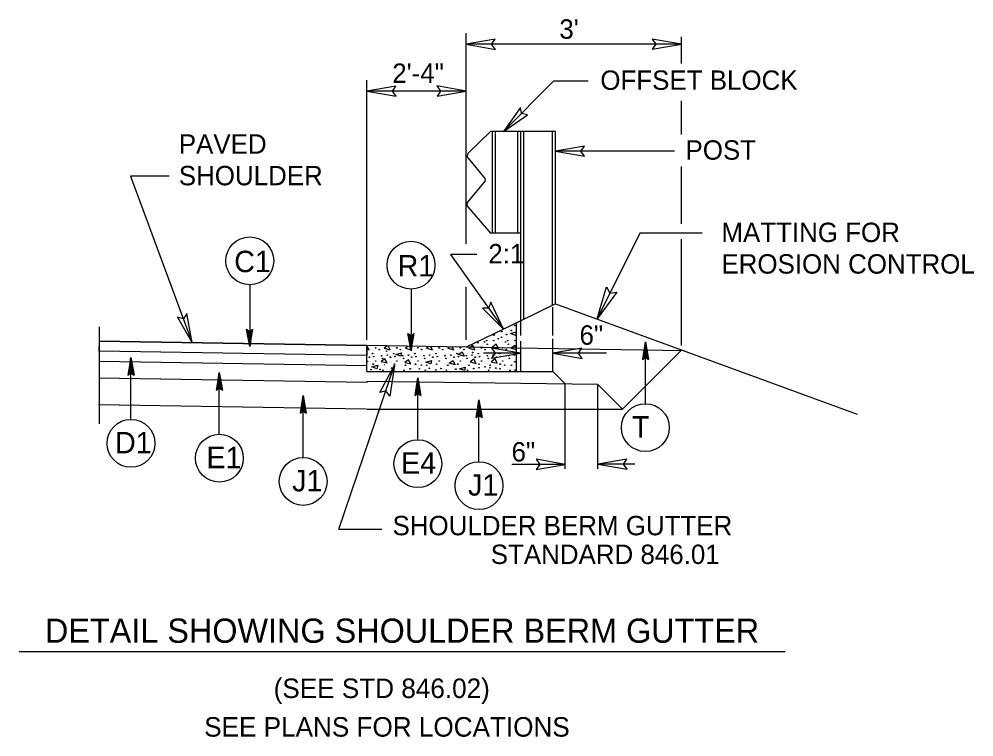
# Model space of a CAD drawing. Extents: x 981824 to 982276, y 44828 to 45204.
# Drawn here: x 982245.3 to 982273.47, y 45182.68 to 45203.85 of the extents above; entities that cross this region are included whole.
import ezdxf

# ---------------------------------------------------------------- set-up
doc = ezdxf.new("R2010")
doc.units = 0
for name, color, linetype in [('Old_Level_1', 7, 'Continuous'), ('Old_Level_2', 7, 'Continuous'), ('Old_Level_20', 7, 'Continuous'), ('Old_Level_3', 7, 'Continuous'), ('Typical Terminator CELL', 7, 'Continuous')]:
    doc.layers.add(name, color=color, linetype=linetype)

msp = doc.modelspace()

# ---------------------------------------------------------------- linework, layer by layer
at = {"layer": 'Old_Level_1'}
for p, q in [((982258.487, 45197.225), (982258.487, 45203.433)), ((982264.837, 45202.542), (982264.837, 45203.331)), ((982264.837, 45203.112), (982258.487, 45203.112)), ((982255.558, 45194.394), (982255.558, 45202.054)), ((982261.066, 45202.018), (982259.584, 45200.532)), ((982262.083, 45202.018), (982261.066, 45202.018)), ((982258.487, 45201.73), (982255.558, 45201.73)), ((982264.837, 45200.446), (982264.837, 45201.441)), ((982258.547, 45199.898), (982259.201, 45200.532)), ((982261.121, 45200.532), (982259.201, 45200.532)), ((982259.267, 45197.534), (982259.267, 45200.532)), ((982259.353, 45197.534), (982259.353, 45200.532)), ((982260.013, 45197.534), (982260.013, 45200.532)), ((982260.1, 45194.956), (982260.1, 45200.532)), ((982260.186, 45194.996), (982260.186, 45200.532)), ((982261.038, 45195.41), (982261.038, 45200.532)), ((982261.121, 45195.454), (982261.121, 45200.532)), ((982264.632, 45199.961), (982261.121, 45199.961)), ((982258.545, 45199.747), (982259.045, 45199.138)), ((982264.837, 45197.816), (982264.837, 45199.501)), ((982249.723, 45199.222), (982248.588, 45199.222)), ((982248.588, 45199.222), (982250.405, 45194.304)), ((982259.047, 45199.079), (982258.53, 45198.455)), ((982258.533, 45198.317), (982259.201, 45197.534)), ((982260.1, 45197.534), (982259.201, 45197.534)), ((982263.61, 45197.539), (982262.348, 45195.006)), ((982265.451, 45197.539), (982263.61, 45197.539)), ((982264.837, 45194.227), (982264.837, 45197.356)), ((982258.803, 45196.91), (982258.026, 45196.91)), ((982258.026, 45196.91), (982259.584, 45194.707)), ((982258.487, 45194.394), (982258.487, 45195.958)), ((982261.121, 45195.454), (982260.1, 45194.953)), ((982261.121, 45195.454), (982270.021, 45192.202)), ((982261.121, 45195.444), (982261.121, 45195.454)), ((982261.047, 45194.52), (982261.047, 45195.356)), ((982260.1, 45194.956), (982258.487, 45194.172)), ((982259.973, 45193.458), (982259.973, 45194.896)), ((982260.1, 45194.52), (982260.1, 45194.956)), ((982252.102, 45194.19), (982252.009, 45194.71)), ((982252.009, 45194.71), (982252.102, 45194.639)), ((982252.027, 45194.7), (982252.102, 45194.19)), ((982252.102, 45194.19), (982252.036, 45194.689)), ((982252.05, 45194.678), (982252.102, 45194.19)), ((982252.102, 45194.19), (982252.065, 45194.671)), ((982252.079, 45194.66), (982252.102, 45194.19)), ((982252.102, 45194.19), (982252.087, 45194.651)), ((982252.102, 45194.19), (982252.191, 45194.71)), ((982252.102, 45194.639), (982252.191, 45194.71)), ((982252.102, 45194.19), (982252.18, 45194.7)), ((982252.168, 45194.689), (982252.102, 45194.19)), ((982252.102, 45194.19), (982252.153, 45194.678)), ((982252.139, 45194.671), (982252.102, 45194.19)), ((982252.102, 45194.19), (982252.128, 45194.66)), ((982252.114, 45194.651), (982252.102, 45194.19)), ((982252.102, 45194.639), (982252.102, 45194.19)), ((982256.86, 45194.064), (982256.765, 45194.58)), ((982256.765, 45194.58), (982256.86, 45194.514)), ((982256.782, 45194.573), (982256.86, 45194.064)), ((982256.86, 45194.064), (982256.794, 45194.564)), ((982256.808, 45194.552), (982256.86, 45194.064)), ((982256.86, 45194.064), (982256.819, 45194.542)), ((982256.831, 45194.536), (982256.86, 45194.064)), ((982256.86, 45194.064), (982256.848, 45194.525)), ((982256.86, 45194.064), (982256.95, 45194.58)), ((982256.86, 45194.514), (982256.95, 45194.58)), ((982256.86, 45194.064), (982256.94, 45194.573)), ((982256.928, 45194.564), (982256.86, 45194.064)), ((982256.86, 45194.064), (982256.914, 45194.552)), ((982256.898, 45194.542), (982256.86, 45194.064)), ((982256.86, 45194.064), (982256.887, 45194.536)), ((982256.871, 45194.525), (982256.86, 45194.064)), ((982259.314, 45194.521), (982259.25, 45194.542)), ((982259.326, 45194.58), (982259.314, 45194.521)), ((982255.558, 45194.221), (982247.668, 45194.351)), ((982256.86, 45194.514), (982256.86, 45194.064)), ((982259.373, 45194.258), (982259.261, 45194.176)), ((982259.44, 45194.134), (982259.373, 45194.258)), ((982260.1, 45193.466), (982260.1, 45194.352)), ((982261.047, 45193.458), (982261.047, 45194.417)), ((982263.775, 45194.331), (982263.685, 45193.814)), ((982263.697, 45193.822), (982263.775, 45194.331)), ((982263.775, 45194.331), (982263.712, 45193.834)), ((982263.723, 45193.842), (982263.775, 45194.331)), ((982263.775, 45194.331), (982263.734, 45193.851)), ((982263.748, 45193.865), (982263.775, 45194.331)), ((982263.775, 45194.331), (982263.76, 45193.871)), ((982263.775, 45194.331), (982263.867, 45193.814)), ((982263.775, 45193.881), (982263.775, 45194.331)), ((982263.789, 45193.871), (982263.775, 45194.331)), ((982263.775, 45194.331), (982263.803, 45193.865)), ((982263.814, 45193.851), (982263.775, 45194.331)), ((982263.775, 45194.331), (982263.826, 45193.842)), ((982263.839, 45193.834), (982263.775, 45194.331)), ((982263.775, 45194.331), (982263.853, 45193.822)), ((982247.655, 45193.958), (982247.655, 45191.909)), ((982255.558, 45193.93), (982247.663, 45194.06)), ((982255.558, 45193.458), (982255.558, 45194.221)), ((982258.487, 45194.172), (982255.558, 45194.221)), ((982255.558, 45193.829), (982255.558, 45194.218)), ((982255.627, 45194.098), (982255.558, 45194.215)), ((982255.558, 45194.112), (982255.627, 45194.098)), ((982256.16, 45194.212), (982256.068, 45194.142)), ((982256.068, 45194.142), (982256.249, 45194.098)), ((982256.249, 45194.098), (982256.185, 45194.212)), ((982256.77, 45194.2), (982256.693, 45194.142)), ((982256.693, 45194.142), (982256.874, 45194.098)), ((982256.874, 45194.098), (982256.818, 45194.2)), ((982257.384, 45194.189), (982257.317, 45194.142)), ((982257.317, 45194.142), (982257.496, 45194.098)), ((982257.496, 45194.098), (982257.447, 45194.186)), ((982257.991, 45194.178), (982257.942, 45194.142)), ((982257.942, 45194.142), (982258.123, 45194.098)), ((982258.123, 45194.098), (982258.078, 45194.176)), ((982259.973, 45194.148), (982258.487, 45194.172)), ((982258.68, 45194.222), (982258.566, 45194.142)), ((982258.566, 45194.142), (982258.746, 45194.098)), ((982258.746, 45194.098), (982258.68, 45194.222)), ((982260.093, 45193.995), (982259.002, 45193.995)), ((982259.261, 45194.176), (982259.44, 45194.134)), ((982259.927, 45194.222), (982259.812, 45194.142)), ((982259.812, 45194.142), (982259.973, 45194.105)), ((982259.973, 45194.141), (982259.927, 45194.222)), ((982264.92, 45194.066), (982259.973, 45194.148)), ((982262.626, 45193.995), (982261.047, 45193.995)), ((982264.818, 45194.067), (982263.102, 45192.347)), ((982255.558, 45193.625), (982247.658, 45193.755)), ((982248.596, 45193.867), (982248.506, 45193.347)), ((982248.521, 45193.359), (982248.596, 45193.867)), ((982248.596, 45193.867), (982248.533, 45193.37)), ((982248.544, 45193.376), (982248.596, 45193.867)), ((982248.596, 45193.867), (982248.558, 45193.388)), ((982248.572, 45193.395), (982248.596, 45193.867)), ((982248.596, 45193.867), (982248.584, 45193.405)), ((982248.596, 45193.867), (982248.688, 45193.347)), ((982248.596, 45193.417), (982248.596, 45193.867)), ((982248.611, 45193.405), (982248.596, 45193.867)), ((982248.596, 45193.867), (982248.625, 45193.395)), ((982248.64, 45193.388), (982248.596, 45193.867)), ((982248.596, 45193.867), (982248.65, 45193.376)), ((982248.664, 45193.37), (982248.596, 45193.867)), ((982248.596, 45193.867), (982248.677, 45193.359)), ((982256.091, 45193.832), (982255.981, 45193.752)), ((982255.981, 45193.752), (982256.16, 45193.708)), ((982256.16, 45193.708), (982256.091, 45193.832)), ((982256.79, 45193.805), (982256.679, 45193.724)), ((982256.679, 45193.724), (982256.856, 45193.68)), ((982256.856, 45193.68), (982256.79, 45193.805)), ((982258.714, 45193.817), (982258.602, 45193.738)), ((982258.602, 45193.738), (982258.783, 45193.692)), ((982258.783, 45193.692), (982258.714, 45193.817)), ((982259.339, 45193.826), (982259.227, 45193.746)), ((982259.227, 45193.746), (982259.405, 45193.704)), ((982259.405, 45193.704), (982259.339, 45193.826)), ((982263.685, 45193.814), (982263.775, 45193.881)), ((982263.775, 45193.881), (982263.867, 45193.814)), ((982248.506, 45193.347), (982248.596, 45193.417)), ((982248.596, 45193.417), (982248.688, 45193.347)), ((982251.204, 45193.429), (982251.115, 45192.91)), ((982251.129, 45192.92), (982251.204, 45193.429)), ((982251.204, 45193.429), (982251.14, 45192.932)), ((982251.152, 45192.938), (982251.204, 45193.429)), ((982251.204, 45193.429), (982251.166, 45192.949)), ((982251.181, 45192.956), (982251.204, 45193.429)), ((982251.204, 45193.429), (982251.192, 45192.967)), ((982251.204, 45193.429), (982251.296, 45192.91)), ((982251.204, 45192.978), (982251.204, 45193.429)), ((982251.218, 45192.967), (982251.204, 45193.429)), ((982251.204, 45193.429), (982251.232, 45192.956)), ((982251.247, 45192.949), (982251.204, 45193.429)), ((982251.204, 45193.429), (982251.259, 45192.938)), ((982251.271, 45192.932), (982251.204, 45193.429)), ((982251.204, 45193.429), (982251.284, 45192.92)), ((982254.73, 45188.8), (982256.372, 45193.639)), ((982255.558, 45193.458), (982259.973, 45193.458)), ((982259.973, 45193.458), (982261.047, 45193.458)), ((982261.047, 45193.458), (982261.412, 45193.091)), ((982255.558, 45193.127), (982247.651, 45193.257)), ((982262.375, 45193.075), (982255.558, 45193.162)), ((982255.558, 45193.162), (982255.558, 45193.127)), ((982257.059, 45193.267), (982256.97, 45192.748)), ((982256.984, 45192.758), (982257.059, 45193.267)), ((982257.059, 45193.267), (982256.995, 45192.77)), ((982257.007, 45192.776), (982257.059, 45193.267)), ((982257.059, 45193.267), (982257.021, 45192.787)), ((982257.036, 45192.794), (982257.059, 45193.267)), ((982257.059, 45193.267), (982257.047, 45192.805)), ((982257.059, 45193.267), (982257.151, 45192.748)), ((982257.059, 45192.816), (982257.059, 45193.267)), ((982257.073, 45192.805), (982257.059, 45193.267)), ((982257.059, 45193.267), (982257.087, 45192.794)), ((982257.102, 45192.787), (982257.059, 45193.267)), ((982257.059, 45193.267), (982257.114, 45192.776)), ((982257.126, 45192.77), (982257.059, 45193.267)), ((982257.059, 45193.267), (982257.139, 45192.758)), ((982251.115, 45192.91), (982251.204, 45192.978)), ((982251.204, 45192.978), (982251.296, 45192.91)), ((982261.412, 45190.581), (982261.412, 45193.091)), ((982262.375, 45193.075), (982263.102, 45192.347)), ((982262.375, 45190.589), (982262.375, 45193.075)), ((982253.676, 45192.744), (982253.587, 45192.225)), ((982253.601, 45192.235), (982253.676, 45192.744)), ((982253.676, 45192.744), (982253.612, 45192.247)), ((982253.624, 45192.253), (982253.676, 45192.744)), ((982253.676, 45192.744), (982253.638, 45192.264)), ((982253.653, 45192.271), (982253.676, 45192.744)), ((982253.676, 45192.744), (982253.664, 45192.282)), ((982253.676, 45192.744), (982253.768, 45192.225)), ((982253.676, 45192.293), (982253.676, 45192.744)), ((982253.69, 45192.282), (982253.676, 45192.744)), ((982253.676, 45192.744), (982253.704, 45192.271)), ((982253.719, 45192.264), (982253.676, 45192.744)), ((982253.676, 45192.744), (982253.731, 45192.253)), ((982253.743, 45192.247), (982253.676, 45192.744)), ((982253.676, 45192.744), (982253.756, 45192.235)), ((982256.97, 45192.748), (982257.059, 45192.816)), ((982257.059, 45192.816), (982257.151, 45192.748)), ((982258.864, 45192.617), (982258.775, 45192.096)), ((982258.789, 45192.108), (982258.864, 45192.617)), ((982258.864, 45192.617), (982258.8, 45192.12)), ((982258.812, 45192.125), (982258.864, 45192.617)), ((982258.864, 45192.617), (982258.827, 45192.137)), ((982258.841, 45192.144), (982258.864, 45192.617)), ((982258.864, 45192.617), (982258.853, 45192.154)), ((982258.864, 45192.617), (982258.956, 45192.096)), ((982258.864, 45192.166), (982258.864, 45192.617)), ((982258.878, 45192.154), (982258.864, 45192.617)), ((982258.864, 45192.617), (982258.893, 45192.144)), ((982258.907, 45192.137), (982258.864, 45192.617)), ((982258.864, 45192.617), (982258.919, 45192.125)), ((982258.932, 45192.12), (982258.864, 45192.617)), ((982258.864, 45192.617), (982258.944, 45192.108)), ((982255.54, 45192.347), (982247.637, 45192.477)), ((982253.587, 45192.225), (982253.676, 45192.293)), ((982253.676, 45192.293), (982253.768, 45192.225)), ((982255.558, 45192.347), (982263.102, 45192.347)), ((982258.775, 45192.096), (982258.864, 45192.166)), ((982258.864, 45192.166), (982258.956, 45192.096)), ((982261.412, 45190.717), (982259.833, 45190.717)), ((982263.465, 45190.725), (982262.375, 45190.725)), ((982254.73, 45188.8), (982255.994, 45188.8))]:
    msp.add_line(p, q, dxfattribs=at)
msp.add_lwpolyline([(982247.655, 45194.772), (982247.655, 45193.882)], dxfattribs=at)
for points in [[(982259.791, 45194.574), (982259.959, 45194.622), (982259.938, 45194.521)], [(982247.668, 45194.351), (982255.558, 45194.221), (982255.558, 45193.93), (982247.663, 45194.06)], [(982256.411, 45193.957), (982256.579, 45194.005), (982256.558, 45193.904)], [(982258.254, 45193.955), (982258.365, 45194.033), (982258.431, 45193.907)], [(982257.296, 45193.734), (982257.464, 45193.782), (982257.443, 45193.681)], [(982257.983, 45193.703), (982258.094, 45193.781), (982258.16, 45193.655)], [(982255.708, 45193.591), (982255.876, 45193.639), (982255.855, 45193.538)], [(982258.289, 45193.534), (982258.457, 45193.582), (982258.436, 45193.481)]]:
    msp.add_lwpolyline(points, close=True, dxfattribs=at)
for centre in [(982259.922, 45194.812), (982259.539, 45194.635), (982259.676, 45194.547), (982259.82, 45194.666), (982258.837, 45194.304), (982259.028, 45194.329), (982259.089, 45194.367), (982259.108, 45194.26), (982259.302, 45194.367), (982259.434, 45194.422), (982259.533, 45194.466), (982259.652, 45194.329), (982259.714, 45194.367), (982259.732, 45194.26), (982259.927, 45194.367), (982255.724, 45193.984), (982255.817, 45194.154), (982255.923, 45194.103), (982256.141, 45194.058), (982256.349, 45193.984), (982256.442, 45194.154), (982256.547, 45194.103), (982256.973, 45193.984), (982257.066, 45194.154), (982257.172, 45194.103), (982257.598, 45193.984), (982257.691, 45194.154), (982257.796, 45194.103), (982258.222, 45193.984), (982258.315, 45194.154), (982258.421, 45194.103), (982258.677, 45194.018), (982258.847, 45193.984), (982258.94, 45194.154), (982259.045, 45194.103), (982259.471, 45193.984), (982259.564, 45194.154), (982259.67, 45194.103), (982255.576, 45193.755), (982255.63, 45193.879), (982255.743, 45193.673), (982255.761, 45193.897), (982255.817, 45193.767), (982255.992, 45193.922), (982256.017, 45193.842), (982256.161, 45193.941), (982256.255, 45193.879), (982256.368, 45193.673), (982256.385, 45193.897), (982256.442, 45193.767), (982256.616, 45193.922), (982256.641, 45193.842), (982256.785, 45193.941), (982256.879, 45193.879), (982256.992, 45193.673), (982257.01, 45193.897), (982257.066, 45193.767), (982257.241, 45193.922), (982257.266, 45193.842), (982257.41, 45193.941), (982257.504, 45193.879), (982257.617, 45193.673), (982257.634, 45193.897), (982257.691, 45193.767), (982257.865, 45193.922), (982257.89, 45193.842), (982258.034, 45193.941), (982258.128, 45193.879), (982258.241, 45193.673), (982258.259, 45193.897), (982258.315, 45193.767), (982258.49, 45193.922), (982258.515, 45193.842), (982258.659, 45193.941), (982258.753, 45193.879), (982258.866, 45193.673), (982258.883, 45193.897), (982258.94, 45193.767), (982259.114, 45193.922), (982259.139, 45193.842), (982259.283, 45193.941), (982259.377, 45193.879), (982259.49, 45193.673), (982259.508, 45193.897), (982259.564, 45193.767), (982259.739, 45193.922), (982259.764, 45193.842), (982259.908, 45193.941), (982259.922, 45193.744), (982255.681, 45193.513), (982255.949, 45193.518), (982256.032, 45193.493), (982256.287, 45193.556), (982256.656, 45193.493), (982256.698, 45193.641), (982256.835, 45193.535), (982257.106, 45193.532), (982257.164, 45193.647), (982257.281, 45193.493), (982257.322, 45193.641), (982257.398, 45193.551), (982257.592, 45193.504), (982257.742, 45193.545), (982257.905, 45193.493), (982257.947, 45193.641), (982258.182, 45193.524), (982258.529, 45193.493), (982258.571, 45193.641), (982258.708, 45193.545), (982258.869, 45193.567), (982259.042, 45193.595), (982259.154, 45193.493), (982259.191, 45193.567), (982259.196, 45193.641), (982259.363, 45193.556), (982259.486, 45193.535), (982259.626, 45193.647), (982259.778, 45193.493), (982259.82, 45193.641), (982259.933, 45193.498)]:
    msp.add_circle(centre, 0.0088, dxfattribs=at)
for centre, radius, start, end in [((982258.626, 45199.82), 0.111, 135.694, 221.3854), ((982259.004, 45199.106), 0.0515, 326.6101, 36.7601), ((982258.621, 45198.388), 0.113, 144.2385, 219.8658), ((982256.073, 45193.641), 0.0088, 351.9822, 186.1383)]:
    msp.add_arc(centre, radius, start, end, dxfattribs=at)
at = {"layer": 'Old_Level_2'}
for p, q in [((982252.102, 45196.018), (982252.102, 45194.19)), ((982256.86, 45195.89), (982256.86, 45194.064)), ((982263.775, 45192.51), (982263.775, 45194.331)), ((982248.596, 45192.04), (982248.596, 45193.867)), ((982251.204, 45191.602), (982251.204, 45193.429)), ((982257.059, 45191.44), (982257.059, 45193.267)), ((982253.676, 45190.917), (982253.676, 45192.744)), ((982258.864, 45190.789), (982258.864, 45192.617))]:
    msp.add_line(p, q, dxfattribs=at)
for centre in [(982252.102, 45196.721), (982256.86, 45196.593), (982263.774, 45191.801), (982248.597, 45191.337), (982251.206, 45190.899), (982257.062, 45190.737), (982253.678, 45190.214), (982258.866, 45190.088)]:
    msp.add_circle(centre, 0.706, dxfattribs=at)
at = {"layer": 'Old_Level_3'}
msp.add_line((982267.904, 45185.19), (982245.296, 45185.19), dxfattribs=at)
at = {"layer": 'Typical Terminator CELL'}
for points in [[(982259.344, 45203.259), (982258.487, 45203.112), (982259.349, 45202.959), (982259.239, 45203.112)], [(982263.979, 45202.964), (982264.837, 45203.112), (982263.974, 45203.264), (982264.084, 45203.112)], [(982256.415, 45201.877), (982255.558, 45201.73), (982256.42, 45201.577), (982256.31, 45201.73)], [(982257.629, 45201.582), (982258.487, 45201.73), (982257.624, 45201.882), (982257.734, 45201.73)], [(982260.086, 45201.242), (982259.584, 45200.532), (982260.301, 45201.033), (982260.116, 45201.064)], [(982261.978, 45200.108), (982261.121, 45199.961), (982261.983, 45199.808), (982261.873, 45199.961)], [(982262.931, 45195.801), (982262.348, 45195.006), (982262.629, 45195.958), (982262.728, 45195.769)], [(982258.969, 45195.322), (982259.584, 45194.707), (982259.212, 45195.499), (982259.15, 45195.322)], [(982249.969, 45195.057), (982250.405, 45194.304), (982250.249, 45195.165), (982250.144, 45195.01)], [(982259.235, 45193.848), (982260.093, 45193.995), (982259.231, 45194.148), (982259.34, 45193.995)], [(982261.904, 45194.143), (982261.047, 45193.995), (982261.909, 45193.843), (982261.799, 45193.995)], [(982255.936, 45192.836), (982256.372, 45193.639), (982256.232, 45192.73), (982256.118, 45192.89)], [(982260.555, 45190.569), (982261.412, 45190.717), (982260.55, 45190.869), (982260.659, 45190.717)], [(982263.232, 45190.873), (982262.375, 45190.725), (982263.237, 45190.573), (982263.128, 45190.725)]]:
    msp.add_lwpolyline(points, close=True, dxfattribs=at)

# ---------------------------------------------------------------- texts
at = {"layer": 'Old_Level_1'}
for s, height, p in [("3'", 0.5717, (982261.237, 45203.273)), ('2\'-4"', 0.5717, (982256.307, 45201.972)), ('OFFSET BLOCK', 0.57168, (982262.446, 45201.766)), ('PAVED', 0.5717, (982250.008, 45199.882)), ('POST', 0.5717, (982264.959, 45199.705)), ('SHOULDER', 0.5717, (982250.008, 45198.95)), ('MATTING FOR', 0.57168, (982266.018, 45197.275)), ('2:1', 0.5716, (982259.141, 45196.646)), ('EROSION CONTROL', 0.57168, (982266.018, 45196.344)), ('6"', 0.5717, (982261.832, 45194.247)), ('6"', 0.5717, (982259.826, 45190.802)), ('SHOULDER BERM GUTTER', 0.57168, (982256.314, 45188.625)), ('STANDARD 846.01', 0.57168, (982259.212, 45187.777)), ('DETAIL SHOWING SHOULDER BERM GUTTER', 0.71446, (982246.059, 45185.453)), ('(SEE STD 846.02)', 0.576, (982252.807, 45183.823)), ('SEE PLANS FOR LOCATIONS', 0.576, (982250.757, 45182.684))]:
    msp.add_text(s, height=height, dxfattribs=at).set_placement(p)
at = {"layer": 'Old_Level_20'}
for s, p in [('C1', (982251.643, 45196.387)), ('R1', (982256.465, 45196.259)), ('T ', (982263.376, 45191.507)), ('D1', (982248.127, 45191.042)), ('E1', (982250.825, 45190.604)), ('E4', (982256.568, 45190.442))]:
    msp.add_text(s, height=0.6316, dxfattribs=at).set_placement(p)
for p in [(982253.354, 45189.919), (982258.542, 45189.795)]:
    msp.add_text('J1', height=0.6316, rotation=360, dxfattribs=at).set_placement(p)

doc.saveas('drawing.dxf')
